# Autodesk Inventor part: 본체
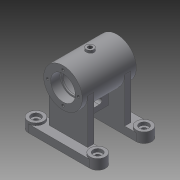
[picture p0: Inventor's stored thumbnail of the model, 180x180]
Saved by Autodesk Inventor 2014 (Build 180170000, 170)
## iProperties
Created: 2015-11
Part Number: 본체
Material: 일반
Document SubType Name: Modeling
Designer: basic
Density: 1 g/cm^3
Appearance: 기본값
Author: basic
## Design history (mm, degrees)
sketch "스케치1"
  geometry: L1 (-40, -40)-(40, -40); L2 (-40, -20)-(40, -20); A1 r 10 centre (-40, -30) between (-40, -40) and (-40, -20); A2 r 10 centre (40, -30) between (40, -40) and (40, -20); 1 further point
  constraints: 4 end point, 4 point on circle, 4 tangent, 2 centre point, 1 equal radius, 1 horizontal alignment
  dimensions: "d0" = 30 vertical distance of point (0, 0) A1.centre; "d1" = 40 horizontal distance of point (0, 0) A1.centre; "d2" = 80 distance of A2.centre A1.centre; "d3" = 20 diameter of A1
extrude "돌출1" new body sketch "스케치1" distance "d4" = 10; taper "d5" = 0 deg
sketch "스케치2"
  geometry: C1 r 10 at (-40, -30); C2 r 10 at (40, -30); A1 r 10 centre (-40, -30) between (-40, -20) and (-40, -40) reference; A2 r 10 centre (40, -30) between (40, -40) and (40, -20) reference; 1 further point
  constraints: 2 centre point, 2 coincident, 2 concentric
extrude "돌출2" join sketch "스케치2" distance "d6" = 3; taper "d7" = 0 deg
sketch "스케치3"
  geometry: C1 r 10 at (0, 0) reference; C2 r 10 at (80, 0) reference; 3 further points
  constraints: 2 coincident
hole "구멍1" sketch "스케치3" at (0, 0), (80, 0) diameter "d8" = 6; stored, may be unused: countersink angle "d12" = 90 deg, drill point angle "d14" = 118 deg; dims "d9" = 6, "d10" = 12, "d11" = 4, "d13" = 8
sketch "스케치5"
  geometry: C1 r 25 at (0, 68); 1 further point
  constraints: 1 centre point, 1 vertical alignment
  dimensions: "d19" = 68 distance of point (0, 0) C1.centre; "d20" = 50 diameter of C1
extrude "돌출4" join sketch "스케치5" stored distance "d21" = 70; taper "d22" = 0 deg
sketch "스케치6"
  geometry: L1 (80, 0)-(0, 0) reference; L2 (65, 0)-(15, 0); L3 (15, 0)-(15, 8); L4 (15, 8)-(65, 8); L5 (65, 8)-(65, 0); 2 further points
  constraints: 8 end point, 2 parallel, 1 horizontal, 1 midpoint, 1 perpendicular, 1 point on line, 1 vertical alignment
  dimensions: "d23" = 50 distance of L3.end L4.end; "d24" = 8 distance between parallel lines of L1 L4
extrude "돌출5" join sketch "스케치6" stored distance "d25" = 70; taper "d26" = 0 deg
sketch "스케치7"
  geometry: L1 (-35, 93)-(35, 93) reference; L2 (35, 93)-(35, 43) reference; L3 (35, 43)-(28, 43) reference; L4 (28, 43)-(28, 10) reference; L5 (28, 10)-(40, 10) reference; L6 (40, 10)-(40, 0) reference; L7 (40, 0)-(20, 0) reference; L8 (20, 0)-(20, 43) reference; L9 (20, 43)-(-20, 43) reference; L10 (-20, 43)-(-20, 0) reference; L11 (-20, 0)-(-40, 0) reference; L12 (-40, 0)-(-40, 10) reference; L13 (-40, 10)-(-28, 10) reference; L14 (-28, 10)-(-28, 43) reference; L15 (-28, 43)-(-35, 43) reference; L16 (-35, 43)-(-35, 93) reference; L17 (-20, 43)-(20, 43); L18 (20, 43)-(20, 23); L19 (20, 23)-(-20, 23); L20 (-20, 23)-(-20, 43); 1 further point
  constraints: 8 end point, 2 parallel, 1 horizontal, 1 perpendicular
  dimensions: "d27" = 20 distance between parallel lines of L19 L17
extrude "돌출6" join sketch "스케치7" stored distance "d28" = 8; taper "d29" = 0 deg
sketch "스케치8"
  geometry: L1 (-92.678, -35)-(-92.678, 35) reference; L2 (-92.678, 35)-(-43.322, 35) reference; L3 (-43.322, 35)-(-43.322, 28) reference; L4 (-43.322, 28)-(-10, 28) reference; L5 (-10, 28)-(-10, 40) reference; L6 (-10, 40)-(0, 40) reference; L7 (0, 40)-(0, 20) reference; L8 (0, 20)-(-23, 20) reference; L9 (-23, 20)-(-23, -20) reference; L10 (-43, -20)-(-23, -20) reference; L11 (-43, -20)-(-43, 20) reference; L12 (-43, 20)-(-43.322, 20) reference; L13 (-43.322, 20)-(-43.322, -20) reference; L14 (-43.322, -20)-(-43, -20) reference; L15 (-43.322, -35)-(-92.678, -35) reference; L16 (-43.322, -28)-(-43.322, -35) reference; L17 (-10, -28)-(-43.322, -28) reference; L18 (-10, -40)-(-10, -28) reference; L19 (0, -40)-(-10, -40) reference; L20 (0, -20)-(0, -40) reference; L21 (-23, -20)-(0, -20) reference; L22 (-23, 20)-(-43, 20) reference; L23 (-36.5, -8)-(-36.5, 8); L24 (-29.5, -8)-(-29.5, 8); A1 r 3.5 centre (-33, -8) between (-36.5, -8) and (-29.5, -8); A2 r 3.5 centre (-33, 8) between (-36.5, 8) and (-29.5, 8); 1 further point
  constraints: 4 end point, 4 point on circle, 3 tangent, 2 centre point, 1 equal radius, 1 perpendicular, 1 vertical alignment
  dimensions: "d30" = 8 vertical distance of A2.centre point (0, 0); "d31" = 16 distance of A1.centre A2.centre; "d32" = 33 distance from line of L7 A2.centre; "d33" = 7 diameter of A2
extrude "돌출7" cut sketch "스케치8" stored distance "d34" = 8; taper "d35" = 0 deg
node "작업 평면1"
sketch "스케치9"
  geometry: C1 r 5 at (40, -40); 1 further point
  constraints: 1 centre point, 1 coincident
  dimensions: "d37" = 10 diameter of C1
extrude "돌출8" join sketch "스케치9" stored distance "d38" = 8; taper "d39" = 0 deg
sketch "스케치10"
  geometry: L1 (-4, 29.5)-(4, 29.5) reference; L2 (4, 29.5)-(4, 23) reference; L3 (4, 23)-(-4, 23) reference; L4 (-4, 23)-(-4, 29.5) reference; L5 (-4, 36.5)-(-4, 43) reference; L6 (-4, 43)-(0, 43) reference; L7 (0, 43)-(4, 43) reference; L8 (4, 43)-(4, 36.5) reference; L9 (4, 36.5)-(-4, 36.5) reference; L10 (-5, 92.495)-(-5, 96) reference; L11 (-5, 96)-(5, 96) reference; L12 (5, 96)-(5, 92.495) reference; L13 (0, 68)-(0, 43); L14 (0, 68)-(12.5, 46.349); L15 (0, 68)-(14, 43.751); L16 (14, 43.751)-(19.196, 46.751); L17 (19.196, 46.751)-(17.331, 49.982); A1 r 25 centre (0, 68) between (0, 43) and (5, 92.495) reference; A2 r 25 centre (0, 68) between (-5, 92.495) and (0, 43) reference; A3 r 25 centre (0, 68) between (5, 92.495) and (0, 43); A4 r 25 centre (0, 68) between (12.5, 46.349) and (17.331, 49.982); 1 further point
  constraints: 11 end point, 6 point on circle, 3 perpendicular, 2 centre point, 1 coincident, 1 collinear, 1 point on line
  dimensions: "d41" = 30 deg angle of L14 L13; "d42" = 28 distance of L13.start L15.end; "d43" = 6 distance of L15.end L16.end
revolve "회전1" sketch "스케치10" stored, may be unused: angle "d44" = 90 deg
sketch "스케치12"
  geometry: 1 further point
sketch "스케치13"
  geometry: C1 r 25 at (0, 0) reference; C2 r 16 at (0, 0); 1 further point
  constraints: 1 centre point, 1 coincident
  dimensions: "d45" = 32 diameter of C2
extrude "돌출9" cut sketch "스케치13" distance "d46" = 12; taper "d47" = 0 deg
sketch "스케치14"
  geometry: C1 r 16 at (0, 0) reference; C2 r 14 at (0, 0); 1 further point
  constraints: 1 centre point, 1 coincident
  dimensions: "d48" = 28 diameter of C2
extrude "돌출10" cut sketch "스케치14" distance "d49" = 2; taper "d50" = 0 deg
sketch "스케치15"
  geometry: C1 r 14 at (0, 0) reference; C2 r 21 at (0, 0); 1 further point
  constraints: 1 centre point, 1 coincident
  dimensions: "d51" = 42 diameter of C2
extrude "돌출11" cut sketch "스케치15" distance "d52" = 42; taper "d53" = 0 deg
sketch "스케치16"
  geometry: C1 r 25 at (0, 0) reference; C2 r 16 at (0, 0); 1 further point
  constraints: 1 centre point, 1 coincident
  dimensions: "d54" = 32 diameter of C2
extrude "돌출12" cut sketch "스케치16" distance "d55" = 12; taper "d56" = 0 deg
sketch "스케치17"
  geometry: C1 r 16 at (0, 0) reference; C2 r 14 at (0, 0); 1 further point
  constraints: 1 centre point, 1 coincident
  dimensions: "d57" = 28 diameter of C2
extrude "돌출13" cut sketch "스케치17" distance "d58" = 2; taper "d59" = 0 deg
sketch "스케치18"
  geometry: C1 r 16 at (0, 0) reference; 2 further points
  constraints: 1 vertical alignment
  dimensions: "d60" = 20 distance of C1.centre point (0, -20)
hole "구멍2" sketch "스케치18" at (0, -20) diameter "d61" = 3.242; stored, may be unused: countersink angle "d65" = 90 deg, drill point angle "d67" = 118 deg; dims "d62" = 8, "d63" = 12, "d64" = 4, "d66" = 10
hole "구멍3" diameter "d73" = 5.188; stored, may be unused: countersink angle "d77" = 90 deg, drill point angle "d79" = 118 deg; dims "d71" = 10, "d72" = 10, "d74" = 8, "d75" = 12, "d76" = 4, "d78" = 10
node "솔리드1"
mirror "대칭1"
mirror "대칭2"
pattern_circular "원형 패턴1" dims angle "d69" = 360 deg
mirror "대칭3"
node "절단 모서리 투영1"
node "절단 모서리 투영2"
node "절단 모서리 투영3"
other parameters: "d36" = -96
